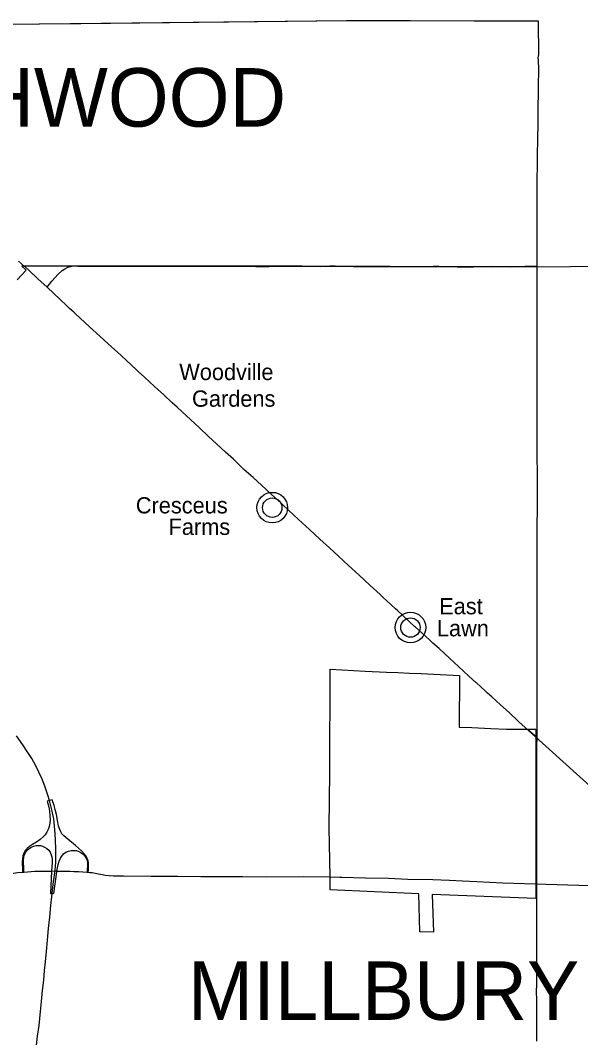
# Model space of a CAD drawing. Extents: x 0 to 851, y 0 to 440.
# Drawn here: x 401.2 to 425.25, y 315.84 to 359.53 of the extents above; entities that cross this region are included whole.
import ezdxf

# ---------------------------------------------------------------- set-up
doc = ezdxf.new("R2010")
doc.units = 0
for name, color, linetype in [('DV_X_Corp_Line', 7, 'Continuous'), ('GM_X_Corporation_Text', 7, 'Continuous'), ('GM_X_County', 7, 'Continuous'), ('GM_X_Interchange_Ramps', 7, 'Continuous'), ('GM_X_Interstate_Route', 7, 'Continuous'), ('GM_X_State_Route', 7, 'Continuous')]:
    doc.layers.add(name, color=color, linetype=linetype)

msp = doc.modelspace()

# ---------------------------------------------------------------- linework, layer by layer
at = {"layer": 'DV_X_Corp_Line'}
msp.add_lwpolyline([(395.425, 359.31), (415.195, 359.534), (423.427, 359.511), (423.438, 358.029), (423.432, 358.018), (423.424, 357.991), (423.42, 357.962), (423.419, 357.934), (423.419, 357.894), (423.42, 357.86), (423.424, 357.8), (423.429, 357.75), (423.432, 357.697), (423.435, 357.573), (423.435, 357.38), (423.428, 356.748), (423.417, 355.476), (423.407, 354.908), (423.402, 354.632), (423.397, 354.385), (423.385, 353.78), (423.382, 353.395), (423.375, 352.599), (423.375, 352.324), (423.374, 351.851), (423.368, 351.418), (423.367, 350.923), (423.368, 350.538), (423.368, 350.342), (423.367, 349.824), (423.368, 349.384), (423.367, 348.959), (422.853, 348.959), (422.23, 348.953), (421.433, 348.96), (420.653, 348.95), (419.946, 348.952), (419.177, 348.959), (418.918, 348.962), (417.787, 348.95), (417.074, 348.966), (416.537, 348.961), (416.351, 348.962), (415.522, 348.966), (414.715, 348.968), (414.479, 348.97), (414.081, 348.964), (413.295, 348.968), (412.965, 348.969), (411.915, 348.969), (411.863, 348.969), (411.393, 348.97), (410.58, 348.972), (410.048, 348.97), (409.095, 348.97), (408.627, 348.97), (408.16, 348.97), (407.731, 348.971), (406.851, 348.973), (406.07, 348.974), (405.125, 348.973), (404.494, 348.976), (404.438, 348.977), (403.669, 348.982), (403.479, 348.975), (401.375, 348.977), (401.26, 348.979), (401.447, 348.807), (401.054, 348.391)], dxfattribs=at)
msp.add_lwpolyline([(414.495, 331.658), (415.998, 331.585), (416.91, 331.542), (417.407, 331.52), (417.909, 331.498), (418.405, 331.472), (418.942, 331.45), (420.055, 331.395), (420.04, 329.169), (420.578, 329.154), (421.397, 329.109), (422.073, 329.093), (423.33, 329.086), (423.321, 321.811), (418.883, 321.992), (418.932, 320.363), (418.346, 320.377), (418.31, 322.01), (414.503, 322.187), (414.496, 322.741), (414.46, 324.847), (414.473, 326.067), (414.486, 327.2)], close=True, dxfattribs=at)
for centre, radius in [((412.011, 338.602), 0.658), ((412.011, 338.602), 0.417), ((417.945, 333.452), 0.658), ((417.945, 333.452), 0.417)]:
    msp.add_circle(centre, radius, dxfattribs=at)
at = {"layer": 'GM_X_County'}
msp.add_lwpolyline([(400.152, 359.363), (403.796, 359.403), (415.195, 359.534), (417.925, 359.526), (423.429, 359.496), (423.438, 358.029), (423.432, 358.018), (423.424, 357.991), (423.42, 357.962), (423.419, 357.934), (423.419, 357.894), (423.42, 357.86), (423.424, 357.8), (423.429, 357.75), (423.432, 357.697), (423.435, 357.573), (423.435, 357.38), (423.428, 356.748), (423.417, 355.476), (423.407, 354.908), (423.402, 354.632), (423.397, 354.385), (423.385, 353.78), (423.382, 353.395), (423.375, 352.599), (423.375, 352.324), (423.374, 351.851), (423.368, 351.418), (423.367, 350.923), (423.368, 350.538), (423.368, 350.342), (423.367, 349.824), (423.368, 349.384), (423.367, 348.959), (423.367, 348.889), (423.367, 348.23), (423.367, 348.069), (423.366, 347.735), (423.366, 347.185), (423.368, 345.976), (423.366, 345.454), (423.367, 345.205), (423.368, 344.849), (423.364, 344.272), (423.366, 343.475), (423.369, 341.001), (423.372, 340.781), (423.373, 340.663), (423.378, 340.232), (423.379, 340.093), (423.382, 339.765), (423.381, 339.435), (423.379, 338.886), (423.377, 338.336), (423.375, 338.034), (423.375, 337.621), (423.369, 337.292), (423.364, 336.137), (423.363, 335.78), (423.363, 335.065), (423.366, 334.104), (423.367, 333.692), (423.369, 332.95), (423.369, 332.593), (423.368, 331.911), (423.367, 331.577), (423.366, 331.283), (423.365, 330.944), (423.365, 330.065), (423.363, 329.653), (423.364, 329.185), (423.364, 329.07), (423.365, 328.833), (423.365, 328.727), (423.361, 328.322), (423.361, 327.744), (423.361, 327.591), (423.36, 327.099), (423.357, 326.869), (423.358, 326.574), (423.357, 326.084), (423.353, 325.598), (423.353, 325.219), (423.354, 324.927), (423.354, 324.827), (423.355, 324.586), (423.354, 324.092), (423.354, 323.741), (423.358, 323.396), (423.359, 322.978), (423.355, 322.748), (423.355, 322.446), (423.356, 322.33), (423.355, 322.231), (423.35, 321.941), (423.35, 321.885), (423.35, 321.874), (423.35, 321.537), (423.352, 321.202), (423.352, 320.923), (423.352, 320.861), (423.349, 320.323), (423.35, 319.646), (423.351, 319.443), (423.351, 319.305), (423.35, 318.753), (423.35, 318.604), (423.35, 318.148), (423.348, 317.791), (423.35, 317.482), (423.35, 317.153), (423.351, 316.828), (423.351, 316.226), (423.352, 315.933), (423.351, 315.684)], dxfattribs=at)
at = {"layer": 'GM_X_Interchange_Ramps'}
for points in [[(402.447, 326.019), (402.351, 325.991), (402.421, 325.734), (402.444, 325.562), (402.464, 325.362), (402.473, 325.201), (402.463, 325.05), (402.433, 324.911), (402.39, 324.784), (402.329, 324.665), (402.263, 324.553), (402.18, 324.458), (402.054, 324.348), (401.893, 324.238), (401.716, 324.129), (401.588, 324.05), (401.485, 323.967), (401.405, 323.869), (401.348, 323.765), (401.31, 323.652), (401.292, 323.533), (401.282, 323.393), (401.288, 323.018), (401.295, 322.946)], [(404.107, 322.943), (404.116, 323.029), (404.128, 323.214), (404.125, 323.335), (404.107, 323.438), (404.071, 323.537), (404.019, 323.634), (403.949, 323.723), (403.826, 323.858), (403.562, 324.085), (403.147, 324.431), (403.059, 324.509), (402.98, 324.596), (402.932, 324.678), (402.886, 324.781), (402.841, 324.923), (402.809, 325.096), (402.75, 325.425), (402.692, 325.636), (402.645, 325.807), (402.566, 326.054), (402.447, 326.019)], [(401.347, 322.95), (401.34, 323.04), (401.333, 323.474), (401.342, 323.568), (401.365, 323.668), (401.398, 323.747), (401.444, 323.831), (401.503, 323.898), (401.565, 323.948), (401.64, 324), (401.71, 324.038), (401.782, 324.067), (401.877, 324.084), (401.96, 324.093), (402.055, 324.085), (402.145, 324.062), (402.239, 324.025), (402.334, 323.962), (402.415, 323.891), (402.478, 323.801), (402.526, 323.696), (402.552, 323.61), (402.564, 323.509), (402.562, 323.352), (402.541, 322.994), (402.486, 322.028), (402.562, 322.019)], [(402.565, 322.043), (402.633, 322.035), (402.757, 322.965), (402.763, 322.994), (402.823, 323.271), (402.864, 323.414), (402.922, 323.546), (402.974, 323.627), (403.056, 323.726), (403.154, 323.798), (403.257, 323.851), (403.381, 323.882), (403.484, 323.88), (403.606, 323.868), (403.708, 323.838), (403.8, 323.791), (403.888, 323.721), (403.967, 323.634), (404.026, 323.54), (404.061, 323.441), (404.085, 323.337), (404.086, 323.248), (404.067, 323.031), (404.059, 322.948)]]:
    msp.add_lwpolyline(points, dxfattribs=at)
at = {"layer": 'GM_X_Interstate_Route'}
for points in [[(402.714, 323.354), (402.719, 323.539), (402.72, 323.962), (402.705, 324.301), (402.697, 324.61), (402.669, 324.919), (402.628, 325.235), (402.548, 325.626), (402.447, 326.019), (402.378, 326.256), (402.251, 326.644), (402.135, 326.935), (401.996, 327.242), (401.861, 327.517), (401.689, 327.828), (401.522, 328.083), (401.304, 328.412), (401.029, 328.806)], [(401.85, 315.108), (401.854, 315.139), (401.881, 315.387), (401.94, 315.895), (401.998, 316.351), (402.065, 316.957), (402.1, 317.386), (402.152, 317.865), (402.199, 318.303), (402.233, 318.719), (402.277, 319.09), (402.315, 319.539), (402.356, 320.022), (402.409, 320.524), (402.457, 321.01), (402.506, 321.506), (402.562, 322.019), (402.565, 322.043), (402.624, 322.537), (402.696, 322.996)], [(402.696, 322.996), (402.71, 323.237), (402.714, 323.352), (402.714, 323.354)]]:
    msp.add_lwpolyline(points, dxfattribs=at)
at = {"layer": 'GM_X_State_Route'}
for points in [[(401.379, 348.963), (401.118, 349.19), (401.112, 349.195)], [(401.573, 348.783), (401.383, 348.96), (401.379, 348.963)], [(403.176, 347.283), (402.906, 347.544), (402.354, 348.067), (401.946, 348.434), (401.573, 348.783)], [(402.354, 348.067), (402.543, 348.328), (402.826, 348.625), (402.987, 348.783), (403.105, 348.861), (403.237, 348.926), (403.361, 348.964), (403.452, 348.986), (403.575, 348.984)], [(403.575, 348.984), (403.669, 348.982), (403.985, 348.982), (404.445, 348.978), (405.522, 348.977)], [(405.522, 348.977), (410.58, 348.972), (411.303, 348.959), (411.878, 348.96), (413.295, 348.968), (414.081, 348.964), (414.459, 348.972), (414.805, 348.979), (415.504, 348.964), (416.351, 348.962), (416.522, 348.963), (417.074, 348.966), (417.881, 348.962), (418.577, 348.966), (418.918, 348.962), (419.177, 348.959), (419.946, 348.952), (420.653, 348.95), (421.433, 348.96), (422.23, 348.953), (432.582, 349.009)], [(403.569, 346.931), (403.499, 346.996), (403.302, 347.162), (403.176, 347.283)], [(406.255, 344.456), (406.186, 344.521), (405.52, 345.141), (404.966, 345.635), (404.615, 345.962), (404.165, 346.376), (403.569, 346.931)], [(414.468, 336.871), (414.053, 337.251), (413.608, 337.661), (413.14, 338.096), (412.709, 338.492), (412.45, 338.733), (412.389, 338.79), (411.958, 339.186), (411.552, 339.562), (411.193, 339.894), (410.794, 340.237), (410.386, 340.644), (410.35, 340.68), (410.009, 340.987), (409.622, 341.344), (409.276, 341.655), (408.881, 342.028), (408.125, 342.735), (407.932, 342.918), (407.721, 343.108), (407.354, 343.452), (406.955, 343.81), (406.521, 344.205), (406.255, 344.456)], [(435.156, 318.06), (422.587, 329.422), (422.175, 329.802), (421.813, 330.133), (421.437, 330.472), (421.257, 330.638), (421.147, 330.739), (420.778, 331.071), (420.757, 331.09), (420.467, 331.353), (420.442, 331.375), (420.01, 331.779), (419.628, 332.128), (419.17, 332.545), (418.912, 332.783), (418.774, 332.908), (418.591, 333.077), (418.455, 333.202), (418.154, 333.47), (418.125, 333.496), (417.68, 333.906), (417.599, 333.981), (417.404, 334.163), (417.304, 334.255), (417.117, 334.429), (417.094, 334.45), (416.768, 334.749), (416.639, 334.867), (416.198, 335.274), (415.723, 335.722), (415.278, 336.122), (414.86, 336.516), (414.468, 336.871)], [(423.365, 328.727), (422.981, 329.064), (422.969, 329.076), (422.965, 329.08)], [(398.354, 322.805), (398.357, 322.805), (398.588, 322.812), (398.95, 322.809), (399.482, 322.807), (399.934, 322.812), (400.226, 322.814), (400.373, 322.825), (400.732, 322.876), (401.075, 322.927), (401.295, 322.946), (401.347, 322.95), (401.819, 322.984), (402.324, 322.992), (402.541, 322.994), (402.696, 322.996)], [(402.696, 322.996), (402.763, 322.994), (402.987, 322.987), (403.319, 322.985), (403.493, 322.98), (403.498, 322.98)], [(403.498, 322.98), (403.7, 322.975), (404.059, 322.948), (404.107, 322.943), (404.187, 322.934)], [(404.187, 322.934), (404.285, 322.924), (404.485, 322.89), (404.712, 322.843), (404.859, 322.817), (405.009, 322.797), (405.203, 322.787), (405.414, 322.784), (405.547, 322.783)], [(405.547, 322.783), (405.548, 322.783), (405.627, 322.783), (406.797, 322.776), (407.948, 322.766), (408.942, 322.765), (409.883, 322.762), (410.063, 322.762), (410.733, 322.761), (411.771, 322.749), (413.365, 322.755), (414.478, 322.739)], [(414.478, 322.739), (414.918, 322.727)], [(414.918, 322.727), (415.001, 322.725), (416.011, 322.704), (416.997, 322.68), (417.837, 322.648), (418.91, 322.624), (419.627, 322.596), (420.185, 322.567), (420.787, 322.544), (421.903, 322.491), (436.8, 322.031)]]:
    msp.add_lwpolyline(points, dxfattribs=at)

# ---------------------------------------------------------------- texts
at = {"layer": 'DV_X_Corp_Line'}
for s, p in [('Woodville', (408.019, 344.082)), ('Gardens', (408.566, 342.937)), ('Cresceus', (406.155, 338.354)), ('Farms', (407.561, 337.431)), ('East', (419.179, 334.021)), ('Lawn', (419.08, 333.074))]:
    msp.add_text(s, height=0.6979, rotation=0, dxfattribs=at).set_placement(p)
at = {"layer": 'GM_X_Corporation_Text'}
for s, p in [('NORTHWOOD', (389.835, 354.969)), ('MILLBURY', (408.386, 316.6))]:
    msp.add_text(s, height=2.5126, rotation=0, dxfattribs=at).set_placement(p)

doc.saveas('drawing.dxf')
